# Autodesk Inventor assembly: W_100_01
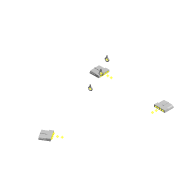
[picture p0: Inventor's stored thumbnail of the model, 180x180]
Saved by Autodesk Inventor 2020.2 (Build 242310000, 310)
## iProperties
Created: 2014-09
Part Number: W_100_01
Document SubType Name: Assembly
Designer: F.Stasiak
Catalog Web Link: www.expertbooks.pl
Manager: www.cadconsulting.pl
Company: Fabian Stasiak CAD Consulting
Author: F.Stasiak
Subject: Zbiór ćwiczeń. Autodesk Inventor 2020. Kurs Professional
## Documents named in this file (3)
- C:\2020_Kurs_Professional\R2 Wiązki\W_100_01.iam
- C:\2020_Kurs_Professional\R2 Wiązki\Komponenty\100-U10.ipt
- C:\2020_Kurs_Professional\R2 Wiązki\Komponenty\Wieszak_01.ipt
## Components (6 placed, 2 different names)
1. 100-U10:1 — Zestawiający:1
2. 100-U10:2 — Zestawiający:2
3. 100-U10:3 — Zestawiający:3
4. Wieszak_01:1 — Równoległy:1
5. Wieszak_01:2
6. Wieszak_01:3 — Równoległy:1
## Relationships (4: Mate 3, Flush 1)
- Zestawiający:1 [Mate]: 100-U10:1
- Zestawiający:2 [Mate]: 100-U10:2
- Zestawiający:3 [Mate]: 100-U10:3
- Równoległy:1 [Flush]: Wieszak_01:1 ↔ Wieszak_01:3
